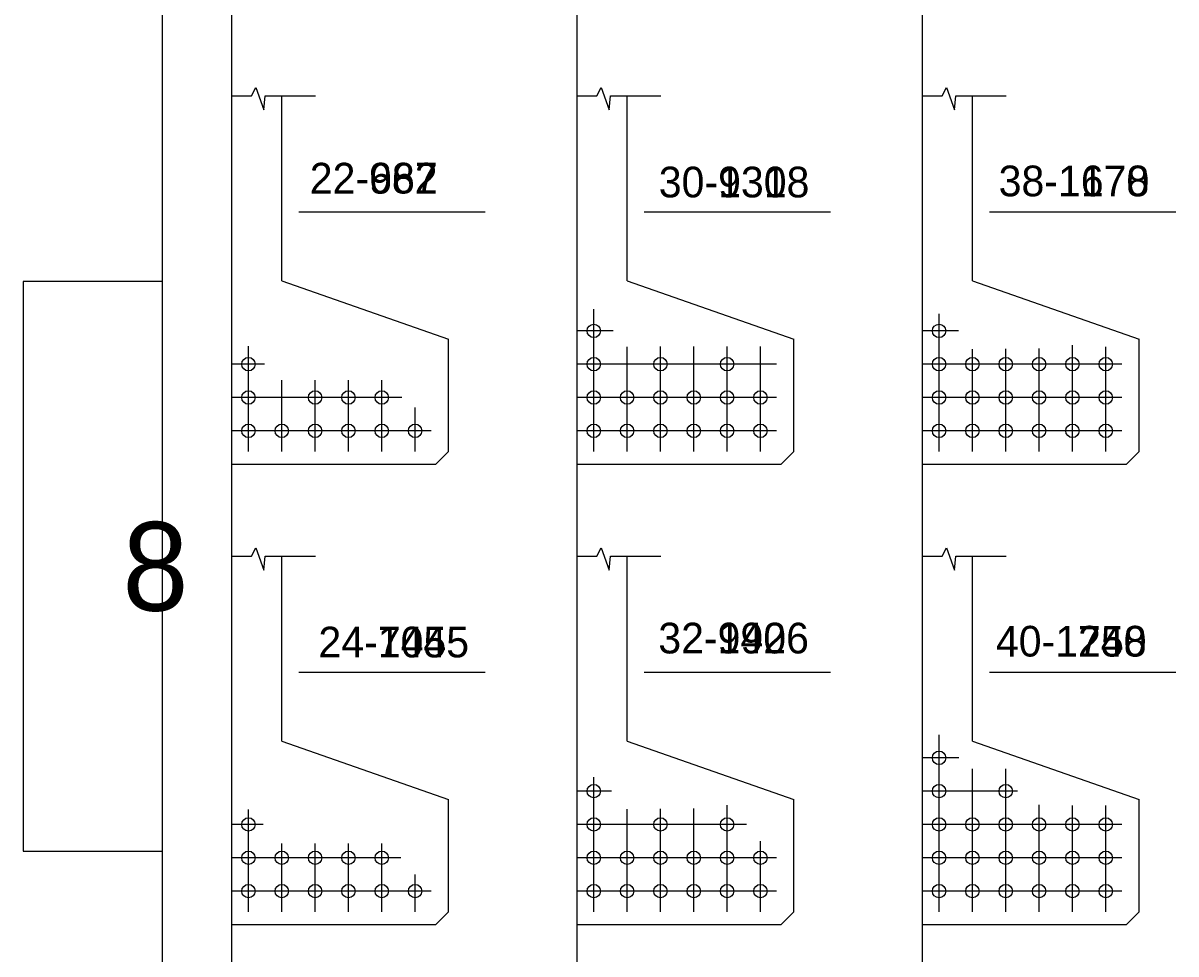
# Model space of a CAD drawing. Extents: x 1005 to 1133, y 2006 to 2074.
# Drawn here: x 1012.25 to 1024.77, y 2019.94 to 2030.05 of the extents above; entities that cross this region are included whole.
import ezdxf

# ---------------------------------------------------------------- set-up
doc = ezdxf.new("R2010")
doc.units = 0
for name, color, linetype in [('Level 1', 7, 'Continuous'), ('Level 8', 7, 'Continuous'), ('Level 9', 7, 'Continuous')]:
    doc.layers.add(name, color=color, linetype=linetype)

msp = doc.modelspace()

# ---------------------------------------------------------------- linework, layer by layer
at = {"layer": 'Level 1'}
msp.add_line((1013.763, 2012.562), (1013.763, 2068.561), dxfattribs=at)
msp.add_lwpolyline([(1013.763, 2027.241), (1012.249, 2027.241), (1012.249, 2021.051), (1013.763, 2021.051)], close=True, dxfattribs=at)
at = {"layer": 'Level 8'}
for p, q in [((1014.516, 2014.747), (1014.516, 2034.639)), ((1018.266, 2014.747), (1018.266, 2034.639)), ((1022.016, 2014.747), (1022.016, 2034.639)), ((1014.729, 2029.258), (1014.776, 2029.347)), ((1014.776, 2029.347), (1014.865, 2029.104)), ((1018.479, 2029.258), (1018.526, 2029.347)), ((1018.526, 2029.347), (1018.615, 2029.104)), ((1022.229, 2029.258), (1022.276, 2029.347)), ((1022.276, 2029.347), (1022.365, 2029.104)), ((1014.516, 2029.258), (1014.729, 2029.258)), ((1014.865, 2029.104), (1014.878, 2029.258)), ((1014.878, 2029.258), (1015.427, 2029.258)), ((1015.06, 2027.248), (1015.06, 2029.258)), ((1018.266, 2029.258), (1018.479, 2029.258)), ((1018.615, 2029.104), (1018.628, 2029.258)), ((1018.628, 2029.258), (1019.177, 2029.258)), ((1018.81, 2027.248), (1018.81, 2029.258)), ((1022.016, 2029.258), (1022.229, 2029.258)), ((1022.365, 2029.104), (1022.378, 2029.258)), ((1022.378, 2029.258), (1022.927, 2029.258)), ((1022.56, 2027.248), (1022.56, 2029.258)), ((1015.244, 2027.998), (1017.269, 2027.998)), ((1018.994, 2027.998), (1021.019, 2027.998)), ((1022.744, 2027.998), (1024.769, 2027.998)), ((1015.06, 2027.248), (1016.869, 2026.614)), ((1018.81, 2027.248), (1020.619, 2026.614)), ((1022.56, 2027.248), (1024.369, 2026.614)), ((1018.447, 2025.392), (1018.447, 2026.941)), ((1022.197, 2025.392), (1022.197, 2026.89)), ((1018.659, 2026.704), (1018.266, 2026.704)), ((1022.408, 2026.704), (1022.016, 2026.704)), ((1016.869, 2025.392), (1016.869, 2026.614)), ((1020.619, 2025.392), (1020.619, 2026.614)), ((1024.369, 2025.392), (1024.369, 2026.614)), ((1014.697, 2025.392), (1014.697, 2026.536)), ((1018.809, 2025.392), (1018.809, 2026.53)), ((1019.171, 2025.392), (1019.171, 2026.534)), ((1019.533, 2025.392), (1019.533, 2026.534)), ((1019.895, 2025.392), (1019.895, 2026.534)), ((1020.257, 2025.392), (1020.257, 2026.534)), ((1022.559, 2025.392), (1022.559, 2026.504)), ((1022.921, 2025.392), (1022.921, 2026.508)), ((1023.283, 2025.392), (1023.283, 2026.512)), ((1023.645, 2025.392), (1023.645, 2026.55)), ((1024.007, 2025.392), (1024.007, 2026.529)), ((1014.87, 2026.342), (1014.516, 2026.342)), ((1020.431, 2026.342), (1018.266, 2026.342)), ((1024.181, 2026.342), (1022.016, 2026.342)), ((1015.059, 2025.392), (1015.059, 2026.167)), ((1015.421, 2025.392), (1015.421, 2026.167)), ((1015.783, 2025.392), (1015.783, 2026.167)), ((1016.145, 2025.392), (1016.145, 2026.167)), ((1016.364, 2025.98), (1014.516, 2025.98)), ((1020.431, 2025.98), (1018.266, 2025.98)), ((1024.181, 2025.98), (1022.016, 2025.98)), ((1016.507, 2025.392), (1016.507, 2025.87)), ((1016.681, 2025.618), (1014.516, 2025.618)), ((1020.431, 2025.618), (1018.266, 2025.618)), ((1024.181, 2025.618), (1022.016, 2025.618)), ((1016.733, 2025.256), (1016.869, 2025.392)), ((1020.483, 2025.256), (1020.619, 2025.392)), ((1024.233, 2025.256), (1024.369, 2025.392)), ((1014.516, 2025.256), (1016.733, 2025.256)), ((1018.266, 2025.256), (1020.483, 2025.256)), ((1022.016, 2025.256), (1024.233, 2025.256)), ((1014.729, 2024.258), (1014.776, 2024.347)), ((1014.776, 2024.347), (1014.865, 2024.104)), ((1018.479, 2024.258), (1018.526, 2024.347)), ((1018.526, 2024.347), (1018.615, 2024.104)), ((1022.229, 2024.258), (1022.276, 2024.347)), ((1022.276, 2024.347), (1022.365, 2024.104)), ((1014.516, 2024.258), (1014.729, 2024.258)), ((1014.865, 2024.104), (1014.878, 2024.258)), ((1014.878, 2024.258), (1015.427, 2024.258)), ((1015.06, 2022.248), (1015.06, 2024.258)), ((1018.266, 2024.258), (1018.479, 2024.258)), ((1018.615, 2024.104), (1018.628, 2024.258)), ((1018.628, 2024.258), (1019.177, 2024.258)), ((1018.81, 2022.248), (1018.81, 2024.258)), ((1022.016, 2024.258), (1022.229, 2024.258)), ((1022.365, 2024.104), (1022.378, 2024.258)), ((1022.378, 2024.258), (1022.927, 2024.258)), ((1022.56, 2022.248), (1022.56, 2024.258)), ((1015.244, 2022.998), (1017.269, 2022.998)), ((1018.994, 2022.998), (1021.019, 2022.998)), ((1022.744, 2022.998), (1024.769, 2022.998)), ((1022.197, 2020.392), (1022.197, 2022.317)), ((1015.06, 2022.248), (1016.869, 2021.614)), ((1018.81, 2022.248), (1020.619, 2021.614)), ((1022.56, 2022.248), (1024.369, 2021.614)), ((1022.413, 2022.066), (1022.016, 2022.066)), ((1022.559, 2020.392), (1022.559, 2021.947)), ((1022.921, 2020.392), (1022.921, 2021.947)), ((1018.447, 2020.392), (1018.447, 2021.856)), ((1018.639, 2021.704), (1018.266, 2021.704)), ((1023.05, 2021.704), (1022.016, 2021.704)), ((1016.869, 2020.392), (1016.869, 2021.614)), ((1020.619, 2020.392), (1020.619, 2021.614)), ((1024.369, 2020.392), (1024.369, 2021.614)), ((1014.697, 2020.392), (1014.697, 2021.503)), ((1018.809, 2020.392), (1018.809, 2021.509)), ((1019.171, 2020.392), (1019.171, 2021.513)), ((1019.533, 2020.392), (1019.533, 2021.517)), ((1019.895, 2020.392), (1019.895, 2021.55)), ((1023.283, 2020.392), (1023.283, 2021.554)), ((1023.645, 2020.392), (1023.645, 2021.547)), ((1024.007, 2020.392), (1024.007, 2021.547)), ((1014.857, 2021.342), (1014.516, 2021.342)), ((1020.107, 2021.342), (1018.266, 2021.342)), ((1024.181, 2021.342), (1022.016, 2021.342)), ((1015.059, 2020.392), (1015.059, 2021.134)), ((1015.421, 2020.392), (1015.421, 2021.134)), ((1015.783, 2020.392), (1015.783, 2021.134)), ((1016.145, 2020.392), (1016.145, 2021.134)), ((1020.257, 2020.392), (1020.257, 2021.159)), ((1016.351, 2020.98), (1014.516, 2020.98)), ((1020.431, 2020.98), (1018.266, 2020.98)), ((1024.181, 2020.98), (1022.016, 2020.98)), ((1016.507, 2020.392), (1016.507, 2020.798)), ((1016.681, 2020.618), (1014.516, 2020.618)), ((1020.431, 2020.618), (1018.266, 2020.618)), ((1024.181, 2020.618), (1022.016, 2020.618)), ((1016.733, 2020.256), (1016.869, 2020.392)), ((1020.483, 2020.256), (1020.619, 2020.392)), ((1024.233, 2020.256), (1024.369, 2020.392)), ((1014.516, 2020.256), (1016.733, 2020.256)), ((1018.266, 2020.256), (1020.483, 2020.256)), ((1022.016, 2020.256), (1024.233, 2020.256))]:
    msp.add_line(p, q, dxfattribs=at)
for centre in [(1018.447, 2026.704), (1022.197, 2026.704), (1014.697, 2026.342), (1018.447, 2026.342), (1019.171, 2026.342), (1022.197, 2026.342), (1022.559, 2026.342), (1022.921, 2026.342), (1023.283, 2026.342), (1023.645, 2026.342), (1024.007, 2026.342), (1014.697, 2025.98), (1015.421, 2025.98), (1015.783, 2025.98), (1016.145, 2025.98), (1018.447, 2025.98), (1018.809, 2025.98), (1019.171, 2025.98), (1019.533, 2025.98), (1019.895, 2025.98), (1020.257, 2025.98), (1022.197, 2025.98), (1022.559, 2025.98), (1022.921, 2025.98), (1023.283, 2025.98), (1023.645, 2025.98), (1024.007, 2025.98), (1014.697, 2025.618), (1015.059, 2025.618), (1015.421, 2025.618), (1015.783, 2025.618), (1016.145, 2025.618), (1016.507, 2025.618), (1018.447, 2025.618), (1018.809, 2025.618), (1019.171, 2025.618), (1019.533, 2025.618), (1019.895, 2025.618), (1020.257, 2025.618), (1022.197, 2025.618), (1022.559, 2025.618), (1022.921, 2025.618), (1023.283, 2025.618), (1023.645, 2025.618), (1024.007, 2025.618), (1022.197, 2022.066), (1018.447, 2021.704), (1022.197, 2021.704), (1014.697, 2021.342), (1018.447, 2021.342), (1019.171, 2021.342), (1019.895, 2021.342), (1022.197, 2021.342), (1022.559, 2021.342), (1022.921, 2021.342), (1023.283, 2021.342), (1023.645, 2021.342), (1024.007, 2021.342), (1014.697, 2020.98), (1015.059, 2020.98), (1015.421, 2020.98), (1015.783, 2020.98), (1016.145, 2020.98), (1018.447, 2020.98), (1018.809, 2020.98), (1019.171, 2020.98), (1019.533, 2020.98), (1019.895, 2020.98), (1020.257, 2020.98), (1022.197, 2020.98), (1022.559, 2020.98), (1022.921, 2020.98), (1023.283, 2020.98), (1023.645, 2020.98), (1024.007, 2020.98), (1014.697, 2020.618), (1015.059, 2020.618), (1015.421, 2020.618), (1015.783, 2020.618), (1016.145, 2020.618), (1016.507, 2020.618), (1018.447, 2020.618), (1018.809, 2020.618), (1019.171, 2020.618), (1019.533, 2020.618), (1019.895, 2020.618), (1020.257, 2020.618), (1022.197, 2020.618), (1022.559, 2020.618), (1022.921, 2020.618), (1023.283, 2020.618), (1023.645, 2020.618), (1024.007, 2020.618)]:
    msp.add_circle(centre, 0.073, dxfattribs=at)
at = {"layer": 'Level 9'}
for p, q in [((1014.516, 2014.747), (1014.516, 2034.639)), ((1018.266, 2014.747), (1018.266, 2034.639)), ((1022.016, 2014.747), (1022.016, 2034.639)), ((1014.729, 2029.258), (1014.776, 2029.347)), ((1014.776, 2029.347), (1014.865, 2029.104)), ((1018.479, 2029.258), (1018.526, 2029.347)), ((1018.526, 2029.347), (1018.615, 2029.104)), ((1022.229, 2029.258), (1022.276, 2029.347)), ((1022.276, 2029.347), (1022.365, 2029.104)), ((1014.516, 2029.258), (1014.729, 2029.258)), ((1014.865, 2029.104), (1014.878, 2029.258)), ((1014.878, 2029.258), (1015.427, 2029.258)), ((1015.06, 2027.248), (1015.06, 2029.258)), ((1018.266, 2029.258), (1018.479, 2029.258)), ((1018.615, 2029.104), (1018.628, 2029.258)), ((1018.628, 2029.258), (1019.177, 2029.258)), ((1018.81, 2027.248), (1018.81, 2029.258)), ((1022.016, 2029.258), (1022.229, 2029.258)), ((1022.365, 2029.104), (1022.378, 2029.258)), ((1022.378, 2029.258), (1022.927, 2029.258)), ((1022.56, 2027.248), (1022.56, 2029.258)), ((1015.244, 2027.998), (1017.269, 2027.998)), ((1018.994, 2027.998), (1021.019, 2027.998)), ((1022.744, 2027.998), (1024.769, 2027.998)), ((1015.06, 2027.248), (1016.869, 2026.614)), ((1018.81, 2027.248), (1020.619, 2026.614)), ((1022.56, 2027.248), (1024.369, 2026.614)), ((1022.197, 2025.392), (1022.197, 2026.89)), ((1022.408, 2026.704), (1022.016, 2026.704)), ((1016.869, 2025.392), (1016.869, 2026.614)), ((1020.619, 2025.392), (1020.619, 2026.614)), ((1024.369, 2025.392), (1024.369, 2026.614)), ((1014.697, 2025.392), (1014.697, 2026.536)), ((1018.447, 2025.392), (1018.447, 2026.53)), ((1018.809, 2025.392), (1018.809, 2026.53)), ((1019.171, 2025.392), (1019.171, 2026.534)), ((1019.533, 2025.392), (1019.533, 2026.534)), ((1019.895, 2025.392), (1019.895, 2026.534)), ((1020.257, 2025.392), (1020.257, 2026.534)), ((1022.559, 2025.392), (1022.559, 2026.504)), ((1022.921, 2025.392), (1022.921, 2026.508)), ((1023.283, 2025.392), (1023.283, 2026.512)), ((1023.645, 2025.392), (1023.645, 2026.55)), ((1024.007, 2025.392), (1024.007, 2026.529)), ((1014.87, 2026.342), (1014.516, 2026.342)), ((1020.431, 2026.342), (1018.266, 2026.342)), ((1024.181, 2026.342), (1022.016, 2026.342)), ((1015.059, 2025.392), (1015.059, 2026.167)), ((1015.421, 2025.392), (1015.421, 2026.167)), ((1015.783, 2025.392), (1015.783, 2026.167)), ((1016.145, 2025.392), (1016.145, 2026.167)), ((1016.364, 2025.98), (1014.516, 2025.98)), ((1020.431, 2025.98), (1018.266, 2025.98)), ((1024.181, 2025.98), (1022.016, 2025.98)), ((1016.507, 2025.392), (1016.507, 2025.87)), ((1016.681, 2025.618), (1014.516, 2025.618)), ((1020.431, 2025.618), (1018.266, 2025.618)), ((1024.181, 2025.618), (1022.016, 2025.618)), ((1016.733, 2025.256), (1016.869, 2025.392)), ((1020.483, 2025.256), (1020.619, 2025.392)), ((1024.233, 2025.256), (1024.369, 2025.392)), ((1014.516, 2025.256), (1016.733, 2025.256)), ((1018.266, 2025.256), (1020.483, 2025.256)), ((1022.016, 2025.256), (1024.233, 2025.256)), ((1014.729, 2024.258), (1014.776, 2024.347)), ((1014.776, 2024.347), (1014.865, 2024.104)), ((1018.479, 2024.258), (1018.526, 2024.347)), ((1018.526, 2024.347), (1018.615, 2024.104)), ((1022.229, 2024.258), (1022.276, 2024.347)), ((1022.276, 2024.347), (1022.365, 2024.104)), ((1014.516, 2024.258), (1014.729, 2024.258)), ((1014.865, 2024.104), (1014.878, 2024.258)), ((1014.878, 2024.258), (1015.427, 2024.258)), ((1015.06, 2022.248), (1015.06, 2024.258)), ((1018.266, 2024.258), (1018.479, 2024.258)), ((1018.615, 2024.104), (1018.628, 2024.258)), ((1018.628, 2024.258), (1019.177, 2024.258)), ((1018.81, 2022.248), (1018.81, 2024.258)), ((1022.016, 2024.258), (1022.229, 2024.258)), ((1022.365, 2024.104), (1022.378, 2024.258)), ((1022.378, 2024.258), (1022.927, 2024.258)), ((1022.56, 2022.248), (1022.56, 2024.258)), ((1015.244, 2022.998), (1017.269, 2022.998)), ((1018.994, 2022.998), (1021.019, 2022.998)), ((1022.744, 2022.998), (1024.769, 2022.998)), ((1015.06, 2022.248), (1016.869, 2021.614)), ((1018.81, 2022.248), (1020.619, 2021.614)), ((1022.56, 2022.248), (1024.369, 2021.614)), ((1022.197, 2020.392), (1022.197, 2021.947)), ((1022.559, 2020.392), (1022.559, 2021.947)), ((1022.921, 2020.392), (1022.921, 2021.947)), ((1018.447, 2020.392), (1018.447, 2021.856)), ((1018.639, 2021.704), (1018.266, 2021.704)), ((1023.05, 2021.704), (1022.016, 2021.704)), ((1016.869, 2020.392), (1016.869, 2021.614)), ((1020.619, 2020.392), (1020.619, 2021.614)), ((1024.369, 2020.392), (1024.369, 2021.614)), ((1014.697, 2020.392), (1014.697, 2021.503)), ((1018.809, 2020.392), (1018.809, 2021.509)), ((1019.171, 2020.392), (1019.171, 2021.513)), ((1019.533, 2020.392), (1019.533, 2021.517)), ((1019.895, 2020.392), (1019.895, 2021.55)), ((1023.283, 2020.392), (1023.283, 2021.554)), ((1023.645, 2020.392), (1023.645, 2021.547)), ((1024.007, 2020.392), (1024.007, 2021.547)), ((1014.857, 2021.342), (1014.516, 2021.342)), ((1020.107, 2021.342), (1018.266, 2021.342)), ((1024.181, 2021.342), (1022.016, 2021.342)), ((1015.059, 2020.392), (1015.059, 2021.134)), ((1015.421, 2020.392), (1015.421, 2021.134)), ((1015.783, 2020.392), (1015.783, 2021.134)), ((1016.145, 2020.392), (1016.145, 2021.134)), ((1020.257, 2020.392), (1020.257, 2021.159)), ((1016.351, 2020.98), (1014.516, 2020.98)), ((1020.431, 2020.98), (1018.266, 2020.98)), ((1024.181, 2020.98), (1022.016, 2020.98)), ((1016.507, 2020.392), (1016.507, 2020.798)), ((1016.681, 2020.618), (1014.516, 2020.618)), ((1020.431, 2020.618), (1018.266, 2020.618)), ((1024.181, 2020.618), (1022.016, 2020.618)), ((1016.733, 2020.256), (1016.869, 2020.392)), ((1020.483, 2020.256), (1020.619, 2020.392)), ((1024.233, 2020.256), (1024.369, 2020.392)), ((1014.516, 2020.256), (1016.733, 2020.256)), ((1018.266, 2020.256), (1020.483, 2020.256)), ((1022.016, 2020.256), (1024.233, 2020.256))]:
    msp.add_line(p, q, dxfattribs=at)
for centre in [(1022.197, 2026.704), (1014.697, 2026.342), (1018.447, 2026.342), (1019.171, 2026.342), (1019.895, 2026.342), (1022.197, 2026.342), (1022.559, 2026.342), (1022.921, 2026.342), (1023.283, 2026.342), (1023.645, 2026.342), (1024.007, 2026.342), (1014.697, 2025.98), (1015.421, 2025.98), (1015.783, 2025.98), (1016.145, 2025.98), (1018.447, 2025.98), (1018.809, 2025.98), (1019.171, 2025.98), (1019.533, 2025.98), (1019.895, 2025.98), (1020.257, 2025.98), (1022.197, 2025.98), (1022.559, 2025.98), (1022.921, 2025.98), (1023.283, 2025.98), (1023.645, 2025.98), (1024.007, 2025.98), (1014.697, 2025.618), (1015.059, 2025.618), (1015.421, 2025.618), (1015.783, 2025.618), (1016.145, 2025.618), (1016.507, 2025.618), (1018.447, 2025.618), (1018.809, 2025.618), (1019.171, 2025.618), (1019.533, 2025.618), (1019.895, 2025.618), (1020.257, 2025.618), (1022.197, 2025.618), (1022.559, 2025.618), (1022.921, 2025.618), (1023.283, 2025.618), (1023.645, 2025.618), (1024.007, 2025.618), (1018.447, 2021.704), (1022.197, 2021.704), (1022.921, 2021.704), (1014.697, 2021.342), (1018.447, 2021.342), (1019.171, 2021.342), (1019.895, 2021.342), (1022.197, 2021.342), (1022.559, 2021.342), (1022.921, 2021.342), (1023.283, 2021.342), (1023.645, 2021.342), (1024.007, 2021.342), (1014.697, 2020.98), (1015.059, 2020.98), (1015.421, 2020.98), (1015.783, 2020.98), (1016.145, 2020.98), (1018.447, 2020.98), (1018.809, 2020.98), (1019.171, 2020.98), (1019.533, 2020.98), (1019.895, 2020.98), (1020.257, 2020.98), (1022.197, 2020.98), (1022.559, 2020.98), (1022.921, 2020.98), (1023.283, 2020.98), (1023.645, 2020.98), (1024.007, 2020.98), (1014.697, 2020.618), (1015.059, 2020.618), (1015.421, 2020.618), (1015.783, 2020.618), (1016.145, 2020.618), (1016.507, 2020.618), (1018.447, 2020.618), (1018.809, 2020.618), (1019.171, 2020.618), (1019.533, 2020.618), (1019.895, 2020.618), (1020.257, 2020.618), (1022.197, 2020.618), (1022.559, 2020.618), (1022.921, 2020.618), (1023.283, 2020.618), (1023.645, 2020.618), (1024.007, 2020.618)]:
    msp.add_circle(centre, 0.073, dxfattribs=at)

# ---------------------------------------------------------------- texts
at = {"layer": 'Level 1'}
msp.add_text('8', height=0.963, dxfattribs=at).set_placement((1013.329, 2023.664))
at = {"layer": 'Level 8'}
for s, p in [('22-682', (1015.363, 2028.196)), ('30-930', (1019.153, 2028.154)), ('38-1178', (1022.844, 2028.166)), ('24-744', (1015.457, 2023.157)), ('32-992', (1019.148, 2023.2)), ('40-1240', (1022.814, 2023.166))]:
    msp.add_text(s, height=0.3333, dxfattribs=at).set_placement(p)
at = {"layer": 'Level 9'}
for s, p in [('22-967', (1015.363, 2028.196)), ('30-1318', (1019.153, 2028.154)), ('38-1670', (1022.844, 2028.166)), ('24-1055', (1015.457, 2023.157)), ('32-1406', (1019.148, 2023.2)), ('40-1758', (1022.814, 2023.166))]:
    msp.add_text(s, height=0.3333, dxfattribs=at).set_placement(p)

doc.saveas('drawing.dxf')
